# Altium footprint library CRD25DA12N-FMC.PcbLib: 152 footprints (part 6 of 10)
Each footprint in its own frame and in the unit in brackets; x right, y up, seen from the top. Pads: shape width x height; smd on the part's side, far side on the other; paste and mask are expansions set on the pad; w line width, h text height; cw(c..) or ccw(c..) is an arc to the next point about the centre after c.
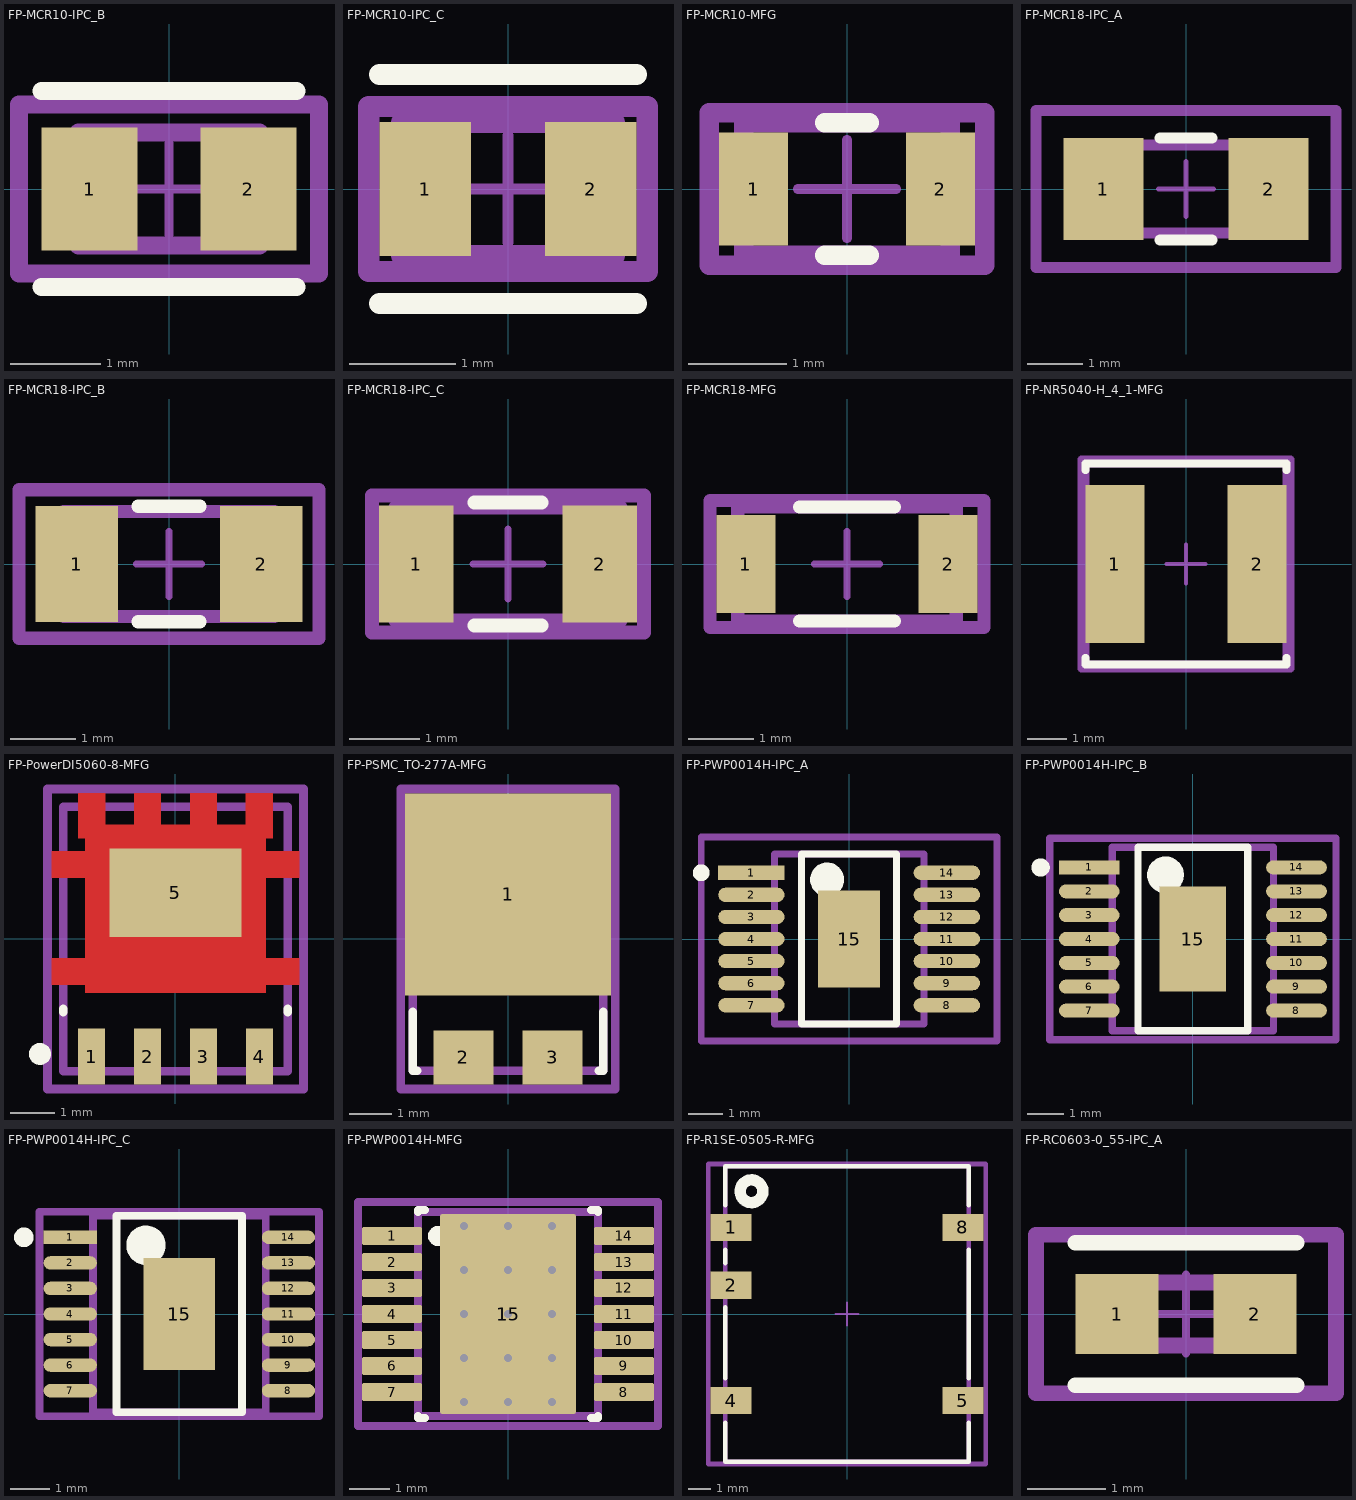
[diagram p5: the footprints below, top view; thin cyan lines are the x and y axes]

## FP-MCR10-IPC_B [mm]
pads (2):
  rect 1.058x1.362 smd paste+0 mask+0: 1(-0.877,0) 2(0.877,0)
Top Overlay:
  lines w0.2: -1.406,-1.081 1.406,-1.081 ; -1.406,1.081 1.406,1.081
Mechanical 5:
  lines w0.2: -1.656,-0.931 1.656,-0.931 1.656,0.931 -1.656,0.931 -1.656,-0.931
  text ".Designator" at 0,0.188 h1
Mechanical 13:
  lines w0.2: -1,-0.625 1,-0.625 1,0.625 -1,0.625 -1,-0.625
Mechanical 15:
  lines w0.2: -1.656,-0.931 1.656,-0.931 1.656,0.931 -1.656,0.931 -1.656,-0.931
Mechanical 16:
  lines w0.1: -0.5,0 0.5,0 ; 0,-0.5 0,0.5
3D body "Res_Rohm_MCR10ERTJ510_eec.STEP": height 0.25, standoff 0, extent -1.656,-0.931 1.656,0.931

## FP-MCR10-IPC_C [mm]
pads (2):
  rect 0.858x1.262 smd paste+0 mask+0: 1(-0.777,0) 2(0.777,0)
Top Overlay:
  lines w0.2: -1.206,-1.075 1.206,-1.075 ; -1.206,1.075 1.206,1.075
Mechanical 5:
  lines w0.2: -1.306,-0.775 -1.306,0.775 1.306,0.775 1.306,-0.775 -1.306,-0.775
  text ".Designator" at 0,0.188 h1
Mechanical 13:
  lines w0.2: -1,-0.625 -1,0.625 1,0.625 1,-0.625 -1,-0.625
Mechanical 15:
  lines w0.2: -1.306,-0.775 -1.306,0.775 1.306,0.775 1.306,-0.775 -1.306,-0.775
Mechanical 16:
  lines w0.1: -0.5,0 0.5,0 ; 0,-0.5 0,0.5
3D body "Res_Rohm_MCR10ERTJ510_eec.STEP": height 0.25, standoff 0, extent -1.306,-0.775 1.306,0.775

## FP-MCR10-MFG [mm]
pads (2):
  rect 0.7x1.15 smd paste+0 mask+0: 1(-0.95,0) 2(0.95,0)
Top Overlay:
  lines w0.2: -0.225,-0.675 0.225,-0.675 ; -0.225,0.675 0.225,0.675
Mechanical 5:
  lines w0.2: -1.4,-0.775 -1.4,0.775 1.4,0.775 1.4,-0.775 -1.4,-0.775
  text ".Designator" at 0,0.188 h1
Mechanical 13:
  lines w0.2: -1.05,-0.675 -1.05,0.675 1.05,0.675 1.05,-0.675 -1.05,-0.675
Mechanical 15:
  lines w0.2: -1.4,-0.775 -1.4,0.775 1.4,0.775 1.4,-0.775 -1.4,-0.775
Mechanical 16:
  lines w0.1: -0.5,0 0.5,0 ; 0,-0.5 0,0.5
3D body "Res_Rohm_MCR10ERTJ510_eec.STEP": height 0.25, standoff 0, extent -1.4,-0.775 1.4,0.775

## FP-MCR18-IPC_A [mm]
pads (2):
  rect 1.456x1.858 smd paste+0 mask+0: 1(-1.501,0) 2(1.501,0)
Top Overlay:
  lines w0.2: -0.473,-0.929 0.473,-0.929 ; -0.473,0.929 0.473,0.929
Mechanical 5:
  lines w0.2: -2.729,-1.429 -2.729,1.429 2.729,1.429 2.729,-1.429 -2.729,-1.429
  text ".Designator" at 0,0.188 h1
Mechanical 13:
  lines w0.2: -1.6,-0.8 -1.6,0.8 1.6,0.8 1.6,-0.8 -1.6,-0.8
Mechanical 15:
  lines w0.2: -2.729,-1.429 -2.729,1.429 2.729,1.429 2.729,-1.429 -2.729,-1.429
Mechanical 16:
  lines w0.1: -0.5,0 0.5,0 ; 0,-0.5 0,0.5
3D body "Res_Rohm_MCR18ERTFL1R10_eec.STEP": height 0.25, standoff 0, extent -2.729,-1.429 2.729,1.429

## FP-MCR18-IPC_B [mm]
pads (2):
  rect 1.256x1.758 smd paste+0 mask+0: 1(-1.401,0) 2(1.401,0)
Top Overlay:
  lines w0.2: -0.473,-0.879 0.473,-0.879 ; -0.473,0.879 0.473,0.879
Mechanical 5:
  lines w0.2: -2.279,-1.129 -2.279,1.129 2.279,1.129 2.279,-1.129 -2.279,-1.129
  text ".Designator" at 0,0.188 h1
Mechanical 13:
  lines w0.2: -1.6,-0.8 -1.6,0.8 1.6,0.8 1.6,-0.8 -1.6,-0.8
Mechanical 15:
  lines w0.2: -2.279,-1.129 -2.279,1.129 2.279,1.129 2.279,-1.129 -2.279,-1.129
Mechanical 16:
  lines w0.1: -0.5,0 0.5,0 ; 0,-0.5 0,0.5
3D body "Res_Rohm_MCR18ERTFL1R10_eec.STEP": height 0.25, standoff 0, extent -2.279,-1.129 2.279,1.129

## FP-MCR18-IPC_C [mm]
pads (2):
  rect 1.056x1.658 smd paste+0 mask+0: 1(-1.301,0) 2(1.301,0)
Top Overlay:
  lines w0.2: -0.473,-0.875 0.473,-0.875 ; -0.473,0.875 0.473,0.875
Mechanical 5:
  lines w0.2: -1.929,-0.975 1.929,-0.975 1.929,0.975 -1.929,0.975 -1.929,-0.975
  text ".Designator" at 0,0.188 h1
Mechanical 13:
  lines w0.2: -1.6,-0.8 1.6,-0.8 1.6,0.8 -1.6,0.8 -1.6,-0.8
Mechanical 15:
  lines w0.2: -1.929,-0.975 1.929,-0.975 1.929,0.975 -1.929,0.975 -1.929,-0.975
Mechanical 16:
  lines w0.1: -0.5,0 0.5,0 ; 0,-0.5 0,0.5
3D body "Res_Rohm_MCR18ERTFL1R10_eec.STEP": height 0.25, standoff 0, extent -1.929,-0.975 1.929,0.975

## FP-MCR18-MFG [mm]
pads (2):
  rect 0.9x1.5 smd paste+0 mask+0: 1(-1.55,0) 2(1.55,0)
Top Overlay:
  lines w0.2: -0.725,-0.875 0.725,-0.875 ; -0.725,0.875 0.725,0.875
Mechanical 5:
  lines w0.2: -2.1,-0.975 -2.1,0.975 2.1,0.975 2.1,-0.975 -2.1,-0.975
  text ".Designator" at 0,0.188 h1
Mechanical 13:
  lines w0.2: -1.675,-0.875 -1.675,0.875 1.675,0.875 1.675,-0.875 -1.675,-0.875
Mechanical 15:
  lines w0.2: -2.1,-0.975 -2.1,0.975 2.1,0.975 2.1,-0.975 -2.1,-0.975
Mechanical 16:
  lines w0.1: -0.5,0 0.5,0 ; 0,-0.5 0,0.5
3D body "Res_Rohm_MCR18ERTFL1R10_eec.STEP": height 0.25, standoff 0, extent -2.1,-0.975 2.1,0.975

## FP-NR5040-H_4_1-MFG [mm]
pads (2):
  rect 1.5x4 smd paste+0 mask+0: 1(-1.8,0) 2(1.8,0)
Top Overlay:
  lines w0.2: -2.55,-2.375 -2.55,-2.55 2.55,-2.55 2.55,-2.375 ; -2.55,2.375 -2.55,2.55 2.55,2.55 2.55,2.375
Mechanical 5:
  lines w0.2: -2.65,-2.65 -2.65,2.65 2.65,2.65 2.65,-2.65 -2.65,-2.65
  text ".Designator" at 0,0.188 h1
Mechanical 13:
  lines w0.2: -2.55,-2.55 -2.55,2.55 2.55,2.55 2.55,-2.55 -2.55,-2.55
Mechanical 15:
  lines w0.2: -2.65,-2.65 -2.65,2.65 2.65,2.65 2.65,-2.65 -2.65,-2.65
Mechanical 16:
  lines w0.1: -0.5,0 0.5,0 ; 0,-0.5 0,0.5
3D body "Ind_Taiyo_Yuden_NR5040T1R5N_eec.STEP": height 0.25, standoff 0, extent -2.65,-2.65 2.65,2.65

## FP-PowerDI5060-8-MFG [mm]
pads (5):
  rect 0.61x1.27 smd paste+0 mask+0: 1(-1.905,-2.67) 2(-0.635,-2.67) 3(0.635,-2.67) 4(1.905,-2.67)
  rect 3x2 smd paste+0 mask+0: 5(0,1.05)
Top Layer:
  region: 2.05,-1.215 -2.05,-1.215 -2.05,-1.035 -2.805,-1.035 -2.805,-0.435 -2.05,-0.435 -2.05,1.39 -2.805,1.39 -2.805,1.99 -2.05,1.99 -2.05,2.285 -2.21,2.285 -2.21,3.305 -1.6,3.305 -1.6,2.595 -0.94,2.595 -0.94,3.305 -0.33,3.305 -0.33,2.595 0.33,2.595 0.33,3.305 0.94,3.305 0.94,2.595 1.6,2.595 1.6,3.305 2.21,3.305 2.21,2.285 2.05,2.285 2.05,1.99 2.805,1.99 2.805,1.39 2.05,1.39 2.05,-0.435 2.805,-0.435 2.805,-1.035 2.05,-1.035
Top Overlay:
  circle w0.25: c-3.075,-2.61 r0.125
  lines w0.2: -2.55,-1.66 -2.55,-1.59 ; 2.55,-1.66 2.55,-1.59
Mechanical 5:
  lines w0.2: -2.905,-3.405 2.905,-3.405 2.905,3.405 -2.905,3.405 -2.905,-3.405
  text ".Designator" at 0,0.188 h1
Mechanical 13:
  lines w0.2: -2.55,-3 2.55,-3 2.55,3 -2.55,3 -2.55,-3
Mechanical 15:
  lines w0.2: -2.905,-3.405 2.905,-3.405 2.905,3.405 -2.905,3.405 -2.905,-3.405
Mechanical 16:
  lines w0.1: -0.5,0 0.5,0 ; 0,-0.5 0,0.5
3D body "Trans_Diodes_DMT12H007LPS-13_eec.STEP": height 0.25, standoff 0, extent -2.905,-3.405 2.905,3.405

## FP-PSMC_TO-277A-MFG [mm]
pads (3):
  rect 4.8x4.72 smd paste+0 mask+0: 1(0,1.04)
  rect 1.4x1.27 smd paste+0 mask+0: 2(-1.04,-2.765) 3(1.04,-2.765)
Top Overlay:
  lines w0.2: -2.225,-1.695 -2.225,-3.075 -2.115,-3.075 ; 2.115,-3.075 2.225,-3.075 2.225,-1.695
Mechanical 5:
  lines w0.2: -2.5,-3.5 -2.5,3.5 2.5,3.5 2.5,-3.5 -2.5,-3.5
  text ".Designator" at 0,0 h1
Mechanical 13:
  lines w0.2: -2.225,-3.075 -2.225,3.075 2.225,3.075 2.225,-3.075 -2.225,-3.075
Mechanical 15:
  lines w0.2: -2.5,-3.5 -2.5,3.5 2.5,3.5 2.5,-3.5 -2.5,-3.5
Mechanical 16:
  lines w0.1: -0.5,0 0.5,0 ; 0,-0.5 0,0.5
3D body "Diode_STMicroelectronics_STPS1045SF_eec.STEP": height 0.25, standoff 0, extent -2.5,-3.5 2.5,3.5

## FP-PWP0014H-IPC_A [mm]
pads (15):
  rect 1.955x0.421 smd paste+0 mask+0: 1(-2.875,1.95)
  rrect100% 1.955x0.421 smd paste+0 mask+0: 2(-2.875,1.3) 3(-2.875,0.65) 4(-2.875,0) 5(-2.875,-0.65) 6(-2.875,-1.3) 7(-2.875,-1.95) 8(2.875,-1.95) 9(2.875,-1.3) 10(2.875,-0.65) 11(2.875,0) 12(2.875,0.65) 13(2.875,1.3) 14(2.875,1.95)
  rect 1.82x2.86 smd paste-1000 mask+0: 15(0,0)
Top Overlay:
  circle w0.25: c-4.353,1.95 r0.125
  circle w0.5: c-0.648,1.75 r0.25
  lines w0.2: -1.398,-2.5 -1.398,2.5 1.398,2.5 1.398,-2.5 -1.398,-2.5
Top Paste:
  rectangle: -0.507,-1.027 0.507,1.027
Mechanical 5:
  lines w0.2: -4.353,-3 -4.353,3 4.353,3 4.353,-3 -4.353,-3
  text ".Designator" at 0,0.188 h1
Mechanical 13:
  lines w0.2: -2.2,-2.5 -2.2,2.5 2.2,2.5 2.2,-2.5 -2.2,-2.5
Mechanical 15:
  lines w0.2: -4.353,-3 -4.353,3 4.353,3 4.353,-3 -4.353,-3
Mechanical 16:
  lines w0.1: -0.5,0 0.5,0 ; 0,-0.5 0,0.5
3D body "IC_Texas_Instruments_ALM2402FQPWPRQ1_eec.STEP": height 0.25, standoff 0, extent -4.353,-3 4.353,3

## FP-PWP0014H-IPC_B [mm]
pads (15):
  rect 1.655x0.381 smd paste+0 mask+0: 1(-2.825,1.95)
  rrect100% 1.655x0.381 smd paste+0 mask+0: 2(-2.825,1.3) 3(-2.825,0.65) 4(-2.825,0) 5(-2.825,-0.65) 6(-2.825,-1.3) 7(-2.825,-1.95) 8(2.825,-1.95) 9(2.825,-1.3) 10(2.825,-0.65) 11(2.825,0) 12(2.825,0.65) 13(2.825,1.3) 14(2.825,1.95)
  rect 1.82x2.86 smd paste-1000 mask+0: 15(0,0)
Top Overlay:
  circle w0.5: c-0.748,1.75 r0.25
  circle w0.25: c-4.153,1.95 r0.125
  lines w0.2: -1.498,-2.5 1.498,-2.5 1.498,2.5 -1.498,2.5 -1.498,-2.5
Top Paste:
  rectangle: -0.507,-1.027 0.507,1.027
Mechanical 5:
  lines w0.2: -3.903,-2.75 3.903,-2.75 3.903,2.75 -3.903,2.75 -3.903,-2.75
  text ".Designator" at 0,0.188 h1
Mechanical 13:
  lines w0.2: -2.2,-2.5 2.2,-2.5 2.2,2.5 -2.2,2.5 -2.2,-2.5
Mechanical 15:
  lines w0.2: -3.903,-2.75 3.903,-2.75 3.903,2.75 -3.903,2.75 -3.903,-2.75
Mechanical 16:
  lines w0.1: -0.5,0 0.5,0 ; 0,-0.5 0,0.5
3D body "IC_Texas_Instruments_ALM2402FQPWPRQ1_eec.STEP": height 0.25, standoff 0, extent -3.903,-2.75 3.903,2.75

## FP-PWP0014H-IPC_C [mm]
pads (15):
  rect 1.355x0.341 smd paste+0 mask+0: 1(-2.775,1.95)
  rrect100% 1.355x0.341 smd paste+0 mask+0: 2(-2.775,1.3) 3(-2.775,0.65) 4(-2.775,0) 5(-2.775,-0.65) 6(-2.775,-1.3) 7(-2.775,-1.95) 8(2.775,-1.95) 9(2.775,-1.3) 10(2.775,-0.65) 11(2.775,0) 12(2.775,0.65) 13(2.775,1.3) 14(2.775,1.95)
  rect 1.82x2.86 smd paste-1000 mask+0: 15(0,0)
Top Overlay:
  circle w0.5: c-0.848,1.75 r0.25
  circle w0.25: c-3.953,1.95 r0.125
  lines w0.2: -1.598,-2.5 1.598,-2.5 1.598,2.5 -1.598,2.5 -1.598,-2.5
Top Paste:
  rectangle: -0.507,-1.027 0.507,1.027
Mechanical 5:
  lines w0.2: -3.553,-2.6 3.553,-2.6 3.553,2.6 -3.553,2.6 -3.553,-2.6
  text ".Designator" at 0,0.188 h1
Mechanical 13:
  lines w0.2: -2.2,-2.5 2.2,-2.5 2.2,2.5 -2.2,2.5 -2.2,-2.5
Mechanical 15:
  lines w0.2: -3.553,-2.6 3.553,-2.6 3.553,2.6 -3.553,2.6 -3.553,-2.6
Mechanical 16:
  lines w0.1: -0.5,0 0.5,0 ; 0,-0.5 0,0.5
3D body "IC_Texas_Instruments_ALM2402FQPWPRQ1_eec.STEP": height 0.25, standoff 0, extent -3.553,-2.6 3.553,2.6

## FP-PWP0014H-MFG [mm]
pads (15):
  rrect22% 1.5x0.45 smd paste+0 mask+0: 1(-2.9,1.95) 2(-2.9,1.3) 3(-2.9,0.65) 4(-2.9,0) 5(-2.9,-0.65) 6(-2.9,-1.3) 7(-2.9,-1.95) 8(2.9,-1.95) 9(2.9,-1.3) 10(2.9,-0.65) 11(2.9,0) 12(2.9,0.65) 13(2.9,1.3) 14(2.9,1.95)
  rrect3% 3.4x5 smd paste-1000 mask-1000: 15(0,0)
via 0,-2.2 diameter 0.5 hole 0.2
via 0,-1.1 diameter 0.5 hole 0.2
via 0,0 diameter 0.5 hole 0.2
via 0,1.1 diameter 0.5 hole 0.2
via 0,2.2 diameter 0.5 hole 0.2
via -1.1,-2.2 diameter 0.5 hole 0.2
via -1.1,-1.1 diameter 0.5 hole 0.2
via -1.1,0 diameter 0.5 hole 0.2
via -1.1,1.1 diameter 0.5 hole 0.2
via -1.1,2.2 diameter 0.5 hole 0.2
via 1.1,-2.2 diameter 0.5 hole 0.2
via 1.1,-1.1 diameter 0.5 hole 0.2
via 1.1,0 diameter 0.5 hole 0.2
via 1.1,1.1 diameter 0.5 hole 0.2
via 1.1,2.2 diameter 0.5 hole 0.2
Top Overlay:
  circle w0.25: c-1.75,1.95 r0.125
  lines w0.2: -2.25,-2.55 -2.25,-2.6 -2.075,-2.6 ; -2.25,2.55 -2.25,2.6 -2.075,2.6 ; 2.075,-2.6 2.25,-2.6 2.25,-2.55 ; 2.075,2.6 2.25,2.6 2.25,2.55
Top Paste:
  region: 0.91,1.38 0.91,-1.38 0.91,-1.39 0.902,-1.408 0.888,-1.422 0.87,-1.43 0.86,-1.43 -0.86,-1.43 -0.87,-1.43 -0.888,-1.422 -0.902,-1.408 -0.91,-1.39 -0.91,-1.38 -0.91,1.38 -0.91,1.39 -0.902,1.408 -0.888,1.422 -0.87,1.43 -0.86,1.43 0.86,1.43 0.87,1.43 0.888,1.422 0.902,1.408 0.91,1.39
Top Solder:
  region: 0.91,1.38 0.91,-1.38 0.91,-1.39 0.902,-1.408 0.888,-1.422 0.87,-1.43 0.86,-1.43 -0.86,-1.43 -0.87,-1.43 -0.888,-1.422 -0.902,-1.408 -0.91,-1.39 -0.91,-1.38 -0.91,1.38 -0.91,1.39 -0.902,1.408 -0.888,1.422 -0.87,1.43 -0.86,1.43 0.86,1.43 0.87,1.43 0.888,1.422 0.902,1.408 0.91,1.39
Mechanical 5:
  lines w0.2: -3.75,-2.8 -3.75,2.8 3.75,2.8 3.75,-2.8 -3.75,-2.8
  text ".Designator" at 0,0.188 h1
Mechanical 13:
  lines w0.2: -2.25,-2.55 -2.25,2.55 2.25,2.55 2.25,-2.55 -2.25,-2.55
Mechanical 15:
  lines w0.2: -3.75,-2.8 -3.75,2.8 3.75,2.8 3.75,-2.8 -3.75,-2.8
Mechanical 16:
  lines w0.1: -0.5,0 0.5,0 ; 0,-0.5 0,0.5
3D body "IC_Texas_Instruments_ALM2402FQPWPRQ1_eec.STEP": height 0.25, standoff 0, extent -3.75,-2.8 3.75,2.8

## FP-R1SE-0505-R-MFG [mm]
pads (5):
  rect 1.8x1.2 smd paste+0 mask+0: 1(-5.1,3.81) 2(-5.1,1.27) 4(-5.1,-3.81) 5(5.1,-3.81) 8(5.1,3.81)
Top Overlay:
  circle w0.5: c-4.2,5.4 r0.5
  lines w0.2: -5.35,-4.785 -5.35,-6.5 5.35,-6.5 5.35,-4.785 ; -5.35,-2.835 -5.35,0.295 ; -5.35,2.245 -5.35,2.835 ; -5.35,4.785 -5.35,6.5 5.35,6.5 5.35,4.785 ; 5.35,-2.835 5.35,2.835
Mechanical 5:
  lines w0.2: -6.1,-6.6 6.1,-6.6 6.1,6.6 -6.1,6.6 -6.1,-6.6
  text ".Designator" at 0,0.188 h1
Mechanical 13:
  lines w0.2: -5.35,-6.5 5.35,-6.5 5.35,6.5 -5.35,6.5 -5.35,-6.5
Mechanical 15:
  lines w0.2: -6.1,-6.6 6.1,-6.6 6.1,6.6 -6.1,6.6 -6.1,-6.6
Mechanical 16:
  lines w0.1: -0.5,0 0.5,0 ; 0,-0.5 0,0.5
3D body "IC_Recom_Power_R1SE-0505-R_eec.STEP": height 0.25, standoff 0, extent -6.1,-6.6 6.1,6.6

## FP-RC0603-0_55-IPC_A [mm]
pads (2):
  rect 1.059x1.012 smd paste+0 mask+0: 1(-0.877,0) 2(0.877,0)
Top Overlay:
  lines w0.2: -1.406,-0.906 1.406,-0.906 ; -1.406,0.906 1.406,0.906
Mechanical 5:
  lines w0.2: -1.906,-1.006 1.906,-1.006 1.906,1.006 -1.906,1.006 -1.906,-1.006
  text ".Designator" at 0,0.188 h1
Mechanical 13:
  lines w0.2: -0.8,-0.4 0.8,-0.4 0.8,0.4 -0.8,0.4 -0.8,-0.4
Mechanical 15:
  lines w0.2: -1.906,-1.006 1.906,-1.006 1.906,1.006 -1.906,1.006 -1.906,-1.006
Mechanical 16:
  lines w0.1: -0.5,0 0.5,0 ; 0,-0.5 0,0.5
3D body "Res_Yageo_RC0603FR-07100KL_eec.STEP": height 0.25, standoff 0, extent -1.906,-1.006 1.906,1.006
